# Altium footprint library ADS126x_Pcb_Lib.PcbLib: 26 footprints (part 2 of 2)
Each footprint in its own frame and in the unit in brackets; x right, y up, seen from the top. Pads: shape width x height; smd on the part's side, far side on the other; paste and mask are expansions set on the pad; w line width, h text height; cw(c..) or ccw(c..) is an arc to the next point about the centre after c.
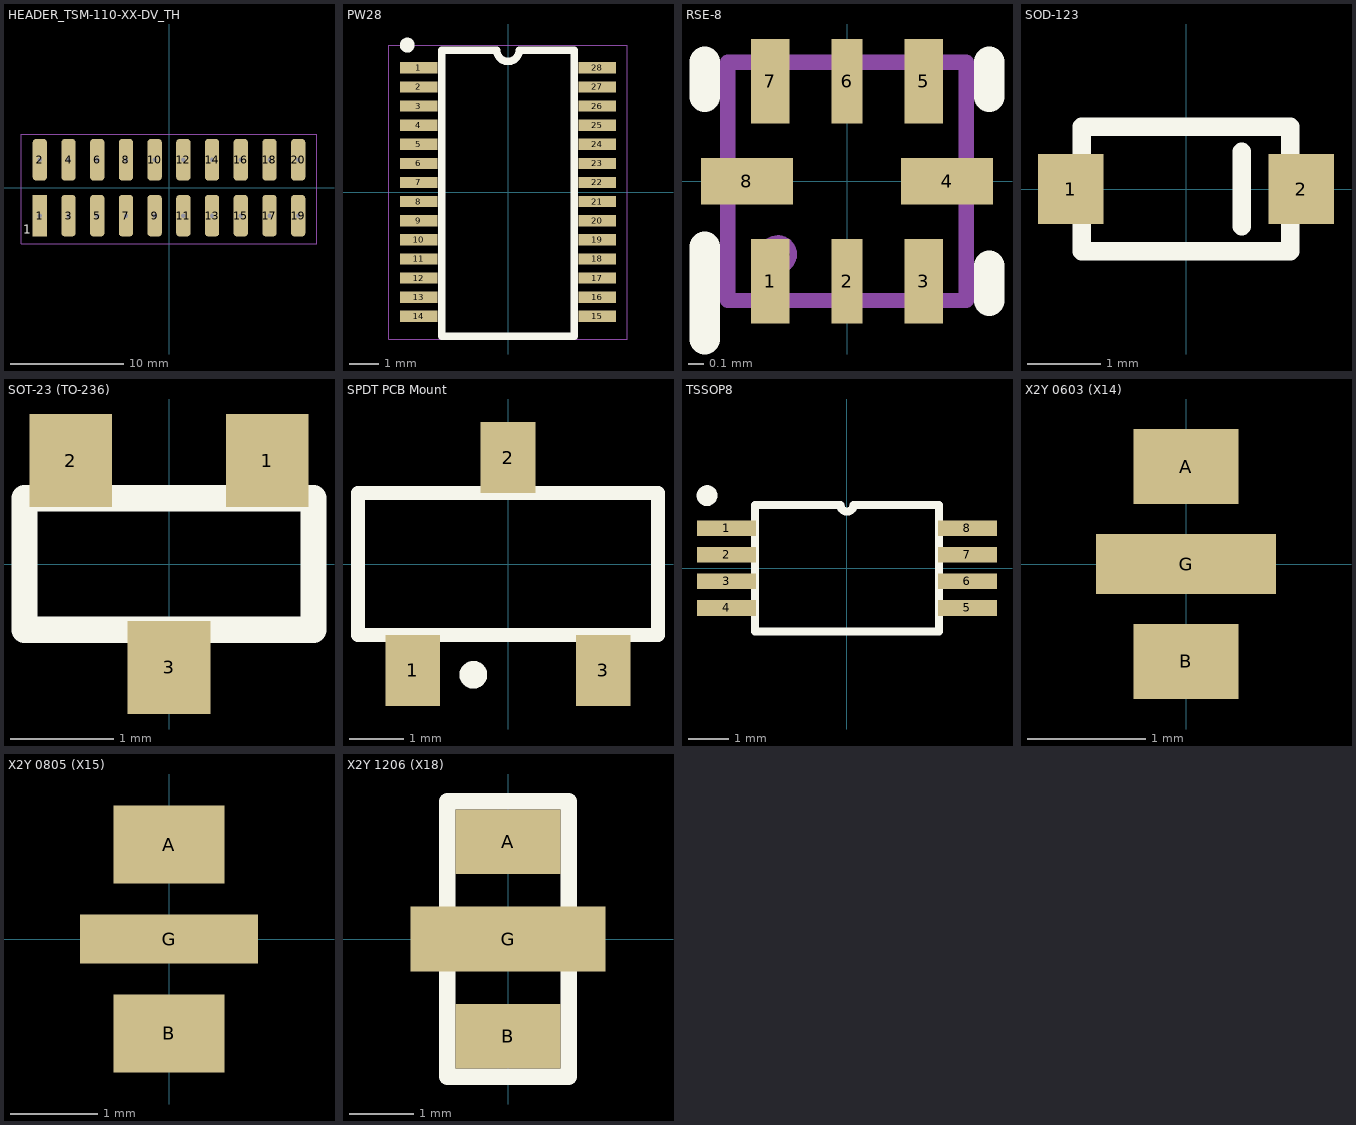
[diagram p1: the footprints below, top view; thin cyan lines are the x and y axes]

## HEADER_TSM-110-XX-DV_TH [mil]
pads (20):
  rect 50x145 hole 15: 1(-450.1,-97.2)
  rrect50% 50x145 hole 15: 2(-450.1,97.8) 3(-350.1,-97.2) 4(-350.1,97.8) 5(-250.1,-97.2) 6(-250.1,97.8) 7(-150.1,-97.2) 8(-150.1,97.8) 9(-50.1,-97.2) 10(-50.1,97.8) 11(49.9,-97.2) 12(49.9,97.8) 13(149.9,-97.2) 14(149.9,97.8) 15(249.9,-97.2) 16(249.9,97.8) 17(349.9,-97.2) 18(349.9,97.8) 19(449.9,-97.2) 20(449.9,97.8)
Top Overlay:
  text "1" at -508.17,-159.7 h30
M15  Courtyards Top:
  lines w1.1: -515.1,-194.2 514.9,-194.2 514.9,185.8 -515.1,185.8 -515.1,-194.2
  text "1" at -508.17,-159.7 h30

## PW28 [mil]
pads (28):
  rect 50.31x15 smd: 1(-119.34,166.4) 2(-119.34,140.8) 3(-119.34,115.2) 4(-119.34,89.6) 5(-119.34,64) 6(-119.34,38.4) 7(-119.34,12.8) 8(-119.34,-12.8) 9(-119.34,-38.4) 10(-119.34,-64) 11(-119.34,-89.6) 12(-119.34,-115.2) 13(-119.34,-140.8) 14(-119.34,-166.4) 15(119.34,-166.4) 16(119.34,-140.8) 17(119.34,-115.2) 18(119.34,-89.6) 19(119.34,-64) 20(119.34,-38.4) 21(119.34,-12.8) 22(119.34,12.8) 23(119.34,38.4) 24(119.34,64.1) 25(119.34,89.6) 26(119.34,115.2) 27(119.34,140.8) 28(119.34,166.5)
Top Overlay:
  circle w10: c-135,196.85 r5
  lines w10: -88.58,-192.91 -88.58,190 -15,190 ccw(c0,190) 15,190 88.58,190 88.58,-192.91 -88.58,-192.91
M15  Courtyards Top:
  lines w1.1: -159.5,-196.85 -159.5,196.85 159.5,196.85 159.5,-196.85 -159.5,-196.85
  text "1" at -140,155 h30

## RSE-8 [mm]
pads (8):
  rect 0.25x0.55 smd: 1(-0.5,-0.65) 3(0.5,-0.65) 5(0.5,0.65) 7(-0.5,0.65)
  rect 0.2x0.55 smd: 2(0,-0.65) 6(0,0.65)
  rect 0.6x0.3 smd: 4(0.65,0) 8(-0.65,0)
Top Overlay:
  lines w0.2: -0.925,-1.025 -0.925,-0.425 ; -0.925,0.55 -0.925,0.775 ; 0.925,-0.775 0.925,-0.55 ; 0.925,0.55 0.925,0.775
M5 Assembly Top:
  circle w0.05: c-0.45,-0.475 r0.1
  lines w0.1: -0.775,-0.775 0.775,-0.775 0.775,0.775 -0.775,0.775 -0.775,-0.775
  text ".Designator" at -0.635,-0.054 h0.36

## SOD-123 [mm]
pads (2):
  rect 0.9x0.95 smd: 1(-1.575,0) 2(1.575,0)
Top Overlay:
  lines w0.254: 0.762,-0.508 0.762,0.508 ; -1.425,-0.85 1.425,-0.85 1.425,0.85 -1.425,0.85 -1.425,-0.85
3D body: height 1.35, standoff 0, extent -1.425,-0.85 1.425,0.85
3D body: height 1.36, standoff 0, extent 0.889,-0.762 1.016,0.762

## SOT-23 (TO-236) [mm]
pads (3):
  rect 0.8x0.9 smd: 1(0.95,1) 2(-0.95,1) 3(0,-1)
Top Overlay:
  lines w0.254: -1.397,-0.635 -1.397,0.635 1.397,0.635 1.397,-0.635 -1.397,-0.635
3D body: height 1.07, standoff 0.05, extent -1.397,-0.635 1.397,0.635

## SPDT PCB Mount [mm]
pads (3):
  rect 1x1.3 smd: 1(-1.75,-1.95) 2(0,1.95) 3(1.75,-1.95)
Top Overlay:
  circle w0.254: c-0.635,-2.032 r0.127
  lines w0.254: -2.75,-1.3 -2.75,1.3 2.75,1.3 2.75,-1.3 -2.75,-1.3
3D body: height 2.51, standoff 0, extent -1,-0.5 0,0.5
3D body: height 2.5, standoff 0, extent -2.75,-1.3 2.75,1.3
3D body: height 2.7, standoff 0, extent 0,-0.5 1,0.5

## TSSOP8 [mm]
pads (8):
  rect 1.45x0.381 smd: 1(-2.95,0.975) 2(-2.95,0.325) 3(-2.95,-0.325) 4(-2.95,-0.975) 5(2.95,-0.975) 6(2.95,-0.325) 7(2.95,0.325) 8(2.95,0.975)
Top Overlay:
  circle w0.254: c-3.429,1.778 r0.127
  lines w0.2: -2.25,-1.55 -2.25,1.55 -0.162,1.55 ccw(c0,1.55) 0.162,1.55 2.25,1.55 2.25,-1.55 -2.25,-1.55
3D body: height 1.2, standoff 0, extent -2.25,-1.55 2.25,1.55
3D body: height 1.2, standoff 0, extent -2.028,0.255 -1.016,1.269

## X2Y 0603 (X14) [mil]
pads (3):
  rect 35x25 smd: A(0,32.5) B(0,-32.5)
  rect 60x20 smd: G(0,0)

## X2Y 0805 (X15) [mil]
pads (3):
  rect 50x35 smd: A(0,42.5) B(0,-42.5)
  rect 80x22 smd: G(0,0)

## X2Y 1206 (X18) [mil]
pads (3):
  rect 65x40 smd: A(0,60) B(0,-60)
  rect 120x40 smd: G(0,0)
Top Overlay:
  lines w10: -37.5,-85 -37.5,85 37.5,85 37.5,-85 -37.5,-85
